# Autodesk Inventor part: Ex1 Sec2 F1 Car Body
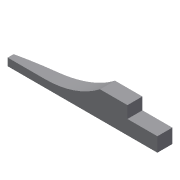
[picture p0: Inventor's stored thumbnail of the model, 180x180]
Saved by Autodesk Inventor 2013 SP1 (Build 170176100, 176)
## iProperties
Created: 2013-01
Part Number: Ex1 Sec2 F1 Car Body
Material: Generic
Document SubType Name: Modeling
Designer: banachd
Density: 1 g/cm^3
Author: banachd
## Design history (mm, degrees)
sketch "Sketch1"
  geometry: L1 (0, 0)-(200, 0); L2 (200, 0)-(200, 20); L3 (200, 20)-(110, 20); L4 (0, 8)-(0, 0); A1 r 510.167 centre (110, -490.167) between (110, 20) and (0, 8)
  constraints: 8 end point, 2 perpendicular, 2 point on circle, 1 centre point, 1 horizontal, 1 parallel, 1 tangent
  dimensions: "d0" = 200 distance of L1.start L1.end; "d1" = 20 distance of L1.end L2.end; "d2" = 90 distance of L2.end L3.end; "d3" = 8 distance of L4.start L1.start
extrude "Extrusion1" new body sketch "Sketch1" distance "d4" = 35; taper "d5" = 0 deg
sketch "Sketch2"
  geometry: L1 (0, 0)-(200, 0) reference; L2 (0, 35)-(200, 35) reference; L3 (0, 0)-(0, 35) reference; L4 (0, 10)-(50, 10); L5 (200, 35)-(160, 35); L6 (160, 35)-(160, 19); L7 (160, 19)-(200, 19); L8 (200, 19)-(200, 35); A1 r 120 centre (50, 130) between (50, 10) and (123.314, 35)
  constraints: 10 end point, 3 parallel, 2 point on circle, 2 point on line, 1 centre point, 1 horizontal, 1 perpendicular, 1 tangent
  dimensions: "d6" = 50 distance of L4.start L4.end; "d7" = 40 distance of L7.end L6.end; "d8" = 16 distance of L6.end L5.end; "d9" = 10 distance between parallel lines of L4 L1; "d10" = 120 radius of A1
extrude "Extrusion2" cut sketch "Sketch2" stored distance "d11" = 0; taper "d12" = 0 deg
body "Solid1"
